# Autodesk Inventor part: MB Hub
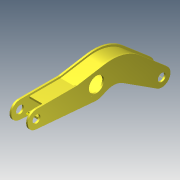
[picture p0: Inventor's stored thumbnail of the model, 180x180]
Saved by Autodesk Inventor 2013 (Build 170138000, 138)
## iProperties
Created: 2012-03
Part Number: MB Hub
Material: Steel, Mild
Document SubType Name: Modeling
Designer: DTS
Density: 7.86 g/cm^3
Mass: 191617 g
Surface Area: 27575.3 cm^2
Volume: 24378.7 cm^3
Author: DTS
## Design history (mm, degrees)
node "Blocks"
  sketch "Weldment"
    geometry: L1 (-698.696, -99.621)-(-13.913, -159.394); L2 (303.472, -136.555)-(697.708, -389.848); L3 (816.698, -229.669)-(500.453, 40.369); L4 (93.224, 153.268)-(-225, 100); L5 (-225, 100)-(-690, 100); L6 (71.528, -143.121)-(105.954, -125.916); L7 (-57.997, -88.254)-(-54.949, -85.206); L8 (-57.997, -85.206)-(-54.949, -88.254); L9 (0, 0)-(-690, 0); L10 (0, 0)-(751.762, -305.717); L11 (0, 0)-(-1018.111, 0); C1 r 75 at (0, 0); C2 r 87 at (0, 0); C3 r 45 at (-690, 0); C4 r 45 at (751.762, -305.717); C5 r 1.524 at (-56.473, -86.73); A1 r 100 centre (-690, 0) between (-690, 100) and (-698.696, -99.621); A2 r 100 centre (751.762, -305.717) between (697.708, -389.848) and (816.698, -229.669); A3 r 500 centre (175.772, -339.871) between (500.453, 40.369) and (93.224, 153.268); A4 r 160 centre (0, 0) between (-13.913, -159.394) and (71.528, -143.121); A5 r 200 centre (195.364, -304.818) between (303.472, -136.555) and (105.954, -125.916); 1 further point
    constraints: 23 end point, 10 centre point, 10 point on circle, 10 tangent, 4 concentric, 1 collinear, 1 horizontal, 1 parallel, 1 perpendicular, 1 other
    dimensions: "d0" = 100 radius of A1; "d2" = 90 diameter of C3; "d3" = 100 radius of A2; "d4" = 90 diameter of C4; "d5" = 690 distance of A1.centre C1.centre; "d6" = 200 radius of A5; "d9" = 160 radius of A4; "d10" = 500 radius of A3; "d11" = 174 diameter of C2; "d12" = 12 radial gap between concentric circles of C1 C2; "d13" = 4.98854 deg angle of L1 L9 (derived); "d14" = 9.50272 deg angle of L4 L9; "d15" = 157.87 deg angle of L10 L9; "d16" = 18.3636 deg angle of L3 L10; "d17" = 10.5905 deg angle of L2 L10; "d18" = 26.5546 deg angle of L6 L9; "d19" = 465 distance of L4.end L5.end; "d40" = 811.54715 distance of L9.start L10.end
  sketch "Connector"
    geometry: L1 (157.164, 27.531)-(232.989, 74.957); L2 (483.604, 231.708)-(512.662, 249.882); L3 (76.449, -64.463)-(145.454, 17.372); L4 (449.028, 351.621)-(398.755, 320.177); L5 (509.104, 419.139)-(460.738, 361.78); L6 (526.921, 255.966)-(571.21, 267.162); L7 (232.989, 74.957)-(483.604, 231.708); L8 (398.755, 320.177)-(93.53, 129.27); L9 (529.743, 443.615)-(509.104, 419.139); L10 (79.271, 123.186)-(-24.509, 96.95); L11 (571.21, 267.162)-(630.701, 282.202); L12 (302.321, 205.82)-(305.369, 208.868); L13 (302.321, 208.868)-(305.369, 205.82); C1 r 45 at (0, 0); C2 r 45 at (606.192, 379.152); C3 r 1.524 at (303.845, 207.344); A1 r 50 centre (539.176, 207.491) between (526.921, 255.966) and (512.662, 249.882); A2 r 50 centre (183.678, -14.86) between (157.164, 27.531) and (145.454, 17.372); A3 r 50 centre (422.514, 394.012) between (449.028, 351.621) and (460.738, 361.78); A4 r 50 centre (67.016, 171.661) between (79.271, 123.186) and (93.53, 129.27); A5 r 100 centre (606.192, 379.152) between (630.701, 282.202) and (529.743, 443.615); A6 r 100 centre (0, 0) between (-24.509, 96.95) and (76.449, -64.463); 1 further point
    constraints: 26 end point, 12 point on circle, 9 centre point
  sketch "Base"
    geometry: L1 (278.529, -481.687)-(299.453, -447.453); L2 (295.917, -416.857)-(172.052, -291.319); L3 (95.022, -681.286)-(272.857, -489.184); L4 (108.329, 19.101)-(158.403, -264.884); L5 (-249.445, -802.646)-(-108.413, 18.617); L6 (3.19, -856.093)-(33.762, -830.109); L7 (48.097, -808.832)-(84.242, -699.551); L8 (-13, -862.043)-(-199.378, -862.043); L9 (37.419, -377.546)-(40.467, -374.498); L10 (37.419, -374.498)-(40.467, -377.546); C1 r 40 at (0, -600); C2 r 40 at (0, 0); C3 r 1.524 at (38.943, -376.022); A1 r 47.5 centre (238, -456.916) between (272.857, -489.184) and (278.529, -481.687); A2 r 25 centre (278.122, -434.416) between (299.453, -447.453) and (295.917, -416.857); A3 r 50 centre (207.644, -256.202) between (158.403, -264.884) and (172.052, -291.319); A4 r 50 centre (131.713, -715.252) between (95.022, -681.286) and (84.242, -699.551); A5 r 110 centre (0, 0) between (108.329, 19.101) and (-108.413, 18.617); A6 r 25 centre (-13, -837.043) between (-15.705, -861.897) and (3.19, -856.093); A7 r 47.5 centre (3, -793.916) between (33.762, -830.109) and (48.097, -808.832); A8 r 50.8 centre (-199.378, -811.243) between (-249.445, -802.646) and (-199.378, -862.043); 1 further point
    constraints: 20 end point, 16 point on circle, 11 centre point
  sketch "CenterSpan"
    geometry: L1 (273.969, -185.044)-(234.974, -284.945); L2 (36.362, 93.155)-(259.933, 5.887); L3 (12.317, -103.463)-(-16.542, -98.622); L4 (180.828, -183.299)-(-38.18, -97.813); L5 (437.598, -26.221)-(296.603, -162.71); L6 (-23.266, 102.39)-(214.339, 156.38); L7 (495.815, 30.136)-(437.598, -26.221); L8 (214.339, 156.38)-(404.104, 199.5); L9 (110.262, -93.996)-(113.31, -90.948); L10 (110.262, -90.948)-(113.31, -93.996); C1 r 82 at (0, 0); C2 r 82 at (223.572, -87.268); C3 r 50 at (426.262, 101.986); C4 r 58.472 at (158.121, -254.947); C5 r 1.524 at (111.786, -92.472); A1 r 90 centre (-2.571, -192.223) between (81.268, -224.948) and (12.317, -103.463); A2 r 60 centre (329.861, -206.861) between (290.003, -162.013) and (273.969, -185.044); A3 r 100 centre (223.572, -87.268) between (290.003, -162.013) and (259.933, 5.887); A4 r 100 centre (0, 0) between (36.362, 93.155) and (-16.542, -98.622); A5 r 105 centre (223.572, -87.268) between (189.942, -186.736) and (296.603, -162.71); A6 r 105 centre (0, 0) between (-23.266, 102.39) and (-38.18, -97.813); A7 r 100 centre (426.262, 101.986) between (495.815, 30.136) and (404.104, 199.5); A8 r 82.5 centre (158.121, -254.947) between (81.268, -224.948) and (234.974, -284.944); 1 further point
    constraints: 20 end point, 16 point on circle, 13 centre point
  sketch "Arm"
    geometry: L1 (-25.496, -107.005)-(137.409, -145.82); L2 (2597.068, -901.099)-(2521.421, -896.025); L3 (2257.231, -771.408)-(2076.35, -579.673); L4 (2076.35, -579.673)-(2063.205, -583.463); L5 (2043.846, -578.704)-(1704.981, -254.849); L6 (1379.251, -95.221)-(16.283, 108.788); L7 (137.409, -145.82)-(1374.243, -440.518); L8 (1601.431, -691.827)-(2199.578, -1052.198); L9 (2469.644, -1123.775)-(2592.355, -1120.82); L10 (1293.329, -509.09)-(1296.377, -506.042); L11 (1293.329, -506.042)-(1296.377, -509.09); C1 r 40.528 at (0, 0); C2 r 40.528 at (2589.706, -1010.852); C3 r 1.524 at (1294.853, -507.566); A1 r 400 centre (2548.19, -496.921) between (2482.623, -891.511) and (2521.421, -896.025); A2 r 110 centre (2589.706, -1010.852) between (2597.994, -1120.539) and (2597.068, -901.099); A3 r 400 centre (2548.19, -496.921) between (2257.231, -771.408) and (2482.623, -891.511); A4 r 20 centre (2057.664, -564.246) between (2043.846, -578.704) and (2063.205, -583.463); A5 r 600 centre (1290.432, -688.61) between (1704.981, -254.849) and (1379.251, -95.221); A6 r 70 centre (1358.018, -508.612) between (1423.227, -534.065) and (1374.243, -440.518); A7 r 100 centre (1516.382, -570.427) between (1423.227, -534.065) and (1519.438, -670.38); A8 r 150 centre (1524.023, -820.31) between (1601.431, -691.827) and (1519.438, -670.38); A9 r 500 centre (2457.606, -623.92) between (2199.578, -1052.198) and (2469.644, -1123.775); A10 r 110 centre (0, 0) between (16.283, 108.788) and (-25.496, -107.005); 1 further point
    constraints: 22 end point, 20 point on circle, 13 centre point
  sketch "Bucket"
    geometry: L1 (0, -20)-(-640.824, -20); L2 (99.176, 0)-(99.176, 10); L3 (-180.824, 0)-(-180.824, 25); L4 (0, 0)-(-180.824, 0); L5 (-180.824, 25)-(69.176, 25); L6 (99.176, 10)-(69.176, 25); L7 (-356.679, 581.068)-(-15.346, 25); L8 (-860.363, 891.232)-(-851.481, 826.214); L9 (-515.824, 1128)-(-836.02, 941.187); L10 (-1280.042, 545.155)-(-976.734, 19.869); L11 (-630.824, -10)-(0, -10); L12 (-630.824, 0)-(0, 0); L13 (-613.369, 1053.537)-(-943.37, 660.257); L14 (-606.842, 1045.759)-(-935.709, 653.829); L15 (0, -20)-(0, -10); L16 (0, -10)-(0, 0); L17 (-356.679, 581.068)-(-508.427, 1102.579); L18 (-511.303, 1112.465)-(-515.824, 1128); L19 (-419.219, 1199.918)-(-425.141, 1166.336); L20 (-409.371, 1198.182)-(-415.292, 1164.599); L21 (-429.989, 1159.412)-(-613.369, 1053.537); L22 (-419.219, 1199.918)-(-409.371, 1198.182); L23 (0, 0)-(99.176, 0); L24 (-606.842, 1045.759)-(-424.989, 1150.752); L25 (-691.058, -5.529)-(-949.951, -5.529); L26 (-1223.594, 696.836)-(-784.605, 849.466); L27 (-1185.527, 84.913)-(-968.841, -1.886); L28 (-1246.2, 229.24)-(-1184.02, 378.858); L29 (-1183.986, 378.801)-(-1121.865, 527.323); L30 (-784.605, 849.466)-(-1109.735, 544.789); C1 r 25 at (-810.824, 898); C2 r 45 at (-1189.112, 597.66); C3 r 40 at (-1144.623, 187.025); A1 r 50 centre (-810.824, 898) between (-836.02, 941.187) and (-860.363, 891.232); A2 r 110 centre (-1144.623, 187.025) between (-1246.2, 229.24) and (-1176.471, 81.737); A3 r 105 centre (-1189.112, 597.66) between (-1223.594, 696.836) and (-1280.042, 545.155); A4 r 408 centre (-630.824, 398) between (-943.37, 660.257) and (-630.824, -10); A5 r 418 centre (-630.824, 398) between (-739.856, -5.529) and (-630.824, -20); A6 r 398 centre (-630.824, 398) between (-935.709, 653.829) and (-630.824, 0); A7 r 10 centre (-434.989, 1168.072) between (-429.989, 1159.412) and (-425.141, 1166.336); A8 r 20 centre (-434.989, 1168.072) between (-424.989, 1150.752) and (-415.292, 1164.599); A9 r 50.8 centre (-949.951, 45.271) between (-968.841, -1.886) and (-949.951, -5.529); A10 r 50.8 centre (-1074.999, 507.721) between (-1109.735, 544.789) and (-1121.865, 527.323); A11 r 50.8 centre (-932.741, 45.271) between (-976.734, 19.869) and (-932.741, -5.529); 1 further point
    constraints: 60 end point, 22 point on circle, 14 centre point
  sketch "FrontBucket"
    geometry: L1 (36.508, 713.207)-(-16.797, 670.2); L2 (-16.797, 670.2)-(-101.739, 335.484); L3 (-101.739, 335.484)-(-109.966, 2.719); L4 (8.288, -109.687)-(308.835, -86.978); L5 (308.835, -86.978)-(319.542, -83.051); L6 (19.324, 520.756)-(99.155, 741.781); L7 (99.155, 741.781)-(80.344, 748.575); L8 (80.344, 748.575)-(36.508, 713.207); L9 (1233.625, 258.517)-(1200.234, 261.682); L10 (1200.234, 261.682)-(1143.868, 239.874); L11 (1143.868, 239.874)-(1177.667, 236.867); L12 (1177.667, 236.867)-(1233.625, 258.517); L13 (967.076, 171.475)-(1143.868, 239.874); L14 (1181.276, 227.541)-(976.097, 148.159); L15 (976.097, 148.159)-(967.076, 171.475); L16 (1237.234, 249.191)-(1233.625, 258.517); L17 (1177.667, 236.867)-(1181.276, 227.541); L18 (1181.276, 227.541)-(1237.234, 249.191); L19 (332.219, -99.88)-(327.869, -88.635); L20 (332.219, -99.88)-(340.093, -96.834); L21 (327.869, -88.635)-(326.446, -84.958); L22 (630.662, 15.585)-(695.946, 40.843); L23 (340.093, -96.834)-(630.662, 15.585); L24 (971.406, 160.283)-(964.544, 144.762); L25 (971.406, 160.283)-(969.963, 164.014); L26 (695.946, 40.843)-(690.173, 55.765); L27 (969.963, 164.014)-(690.173, 55.765); L28 (695.946, 40.843)-(964.544, 144.762); L29 (271.723, 1081.905)-(246.908, 1104.472); L30 (246.908, 1104.472)-(15.69, 814.708); L31 (11.012, 759.335)-(43.462, 700.624); L32 (47.21, 660.849)-(-0.759, 514.651); L33 (556.412, -14.214)-(696.307, 39.911); L34 (696.307, 39.911)-(695.946, 40.843); L35 (594.585, 649.257)-(271.723, 1081.905); L36 (459.694, 596.673)-(459.353, 596.937); L37 (459.353, 596.937)-(498.23, 611.978); L38 (1112.062, 227.901)-(576.694, 642.28); L39 (995.062, 182.294)-(998.041, 183.455); L40 (499.228, 612.083)-(459.694, 596.673); L41 (459.694, 596.673)-(526.939, 544.624); L42 (606.946, 482.699)-(686.952, 420.773); L43 (766.958, 358.848)-(846.965, 296.922); L44 (926.971, 234.997)-(985.819, 189.448); L45 (995.055, 182.3)-(995.062, 182.294); L46 (998.041, 183.455)-(1130.882, 235.237); L47 (985.819, 189.448)-(995.055, 182.3); L48 (1130.882, 235.237)-(595.514, 649.616); C1 r 60 at (0, 0); C2 r 85 at (-189.66, 366.918); C3 r 25 at (54.772, 783.522); C4 r 62.5 at (-189.66, 366.918); A1 r 110 centre (0, 0) between (-109.966, 2.719) and (8.288, -109.687); A2 r 408 centre (403.06, 382.155) between (19.324, 520.756) and (16.94, 513.969); A3 r 50 centre (54.772, 783.522) between (15.69, 814.708) and (11.012, 759.335); A4 r 50 centre (-0.298, 676.437) between (47.21, 660.849) and (43.462, 700.624); A5 r 425 centre (403.06, 382.155) between (-0.759, 514.651) and (556.412, -14.214); 1 further point
    constraints: 96 end point, 10 point on circle, 9 centre point
  sketch "A$C70327705"
    geometry: L1 (1293.342, 14.877)-(652.519, 14.877); L2 (1112.519, 47.877)-(1112.519, 51.877); L3 (652.519, 25)-(652.519, 14.997); L4 (652.519, 0)-(437.177, 0); L5 (437.177, 0)-(416.627, 29.348); L6 (662.519, 24.877)-(652.519, 24.877); L7 (1392.519, 34.877)-(1392.519, 44.877); L8 (1112.519, 34.877)-(1112.519, 59.877); L9 (1293.342, 34.877)-(1112.519, 34.877); L10 (1112.519, 59.877)-(1362.519, 59.877); L11 (1392.519, 44.877)-(1362.519, 59.877); L12 (936.663, 615.946)-(1277.997, 59.877); L13 (432.979, 926.11)-(441.861, 861.091); L14 (777.519, 1162.877)-(457.322, 976.064); L15 (116.871, 116.614)-(247.396, 77.132); L16 (100.413, 392.297)-(47.142, 264.117); L17 (374.881, 853.013)-(360.531, 832.814); L18 (440.113, 873.889)-(374.881, 853.013); L19 (9.07, 588.157)-(247.396, 77.132); L20 (662.519, 24.877)-(1293.342, 24.877); L21 (662.519, 34.877)-(1293.342, 34.877); L22 (679.974, 1088.415)-(349.973, 695.135); L23 (686.501, 1080.636)-(357.633, 688.707); L24 (1293.342, 14.877)-(1293.342, 24.877); L25 (1293.342, 24.877)-(1293.342, 34.877); L26 (936.663, 615.946)-(784.916, 1137.456); L27 (782.039, 1147.342)-(777.519, 1162.877); L28 (874.123, 1234.796)-(868.202, 1201.213); L29 (883.971, 1233.059)-(878.05, 1199.476); L30 (863.354, 1194.289)-(679.974, 1088.415); L31 (874.123, 1234.796)-(883.971, 1233.059); L32 (1293.342, 34.877)-(1392.519, 34.877); L33 (686.501, 1080.636)-(868.354, 1185.629); L34 (652.519, 0)-(652.519, 14.997); L35 (602.285, 29.348)-(293.569, 29.348); L36 (259.584, 50.998)-(247.396, 77.132); L37 (69.748, 731.714)-(508.737, 884.343); C1 r 25 at (482.519, 932.877); C2 r 45 at (104.231, 632.537); A1 r 50 centre (482.519, 932.877) between (457.322, 976.064) and (432.979, 926.11); A2 r 40 centre (148.72, 221.902) between (162.34, 259.512) and (186.286, 208.165); A3 r 110 centre (148.72, 221.902) between (47.142, 264.117) and (116.871, 116.614); A4 r 105 centre (104.231, 632.537) between (69.748, 731.714) and (9.07, 588.157); A5 r 408 centre (662.519, 432.877) between (349.973, 695.135) and (662.519, 24.877); A6 r 398 centre (662.519, 432.877) between (357.633, 688.707) and (662.519, 34.877); A7 r 37.5 centre (293.569, 66.848) between (259.584, 50.998) and (293.569, 29.348); A8 r 10 centre (858.354, 1202.949) between (863.354, 1194.289) and (868.202, 1201.213); A9 r 20 centre (858.354, 1202.949) between (868.354, 1185.629) and (878.05, 1199.476); 1 further point
    constraints: 74 end point, 18 point on circle, 11 centre point
  sketch "A$C60B60B97"
    geometry: 1 further point
sketch "Sketch1"
  geometry: 1 further point
  constraints: 1 other
  node "Weldment:1"
workplane "Work Plane2"
  workplane "Work Plane1"
extrude "Extrusion1" new body sketch "Sketch1" stored distance "d43" = 10; taper "d44" = 0 deg
workplane "Work Plane4"
  workplane "Work Plane3"
extrude "Extrusion2" new body sketch "Sketch1" stored distance "d47" = 10; taper "d48" = 0 deg
sketch "Sketch2"
  geometry: L1 (0, 465)-(0, 0) reference; L2 (53.268, 783.224)-(0, 465) reference; L3 (-329.669, 1506.698)-(-59.631, 1190.453) reference; L4 (-236.555, 993.472)-(-489.848, 1387.708) reference; L5 (-243.121, 761.528)-(-225.916, 795.954) reference; L6 (-199.621, -8.696)-(-259.394, 676.087) reference; L7 (-209.871, 1335.602)-(-74.841, 1177.465); L8 (33.542, 786.526)-(-20, 466.662); L9 (-20, 466.662)-(-20, 107.363); L10 (-429.779, 1331.213)-(-219.728, 1004.283); L11 (-208.026, 787.013)-(-225.231, 752.587); L12 (-239.47, 677.826)-(-188.393, 92.665); L13 (-100, 0)-(-199.621, -8.696); L14 (-188.393, 92.665)-(-20, 107.363); L15 (-243.967, 1352.979)-(-379.3, 1363.646); L16 (-429.779, 1331.213)-(-379.3, 1363.646); C1 r 45 at (-100, 0) reference; C2 r 45 at (-405.717, 1441.762) reference; A1 r 500 centre (-439.871, 865.772) between (53.268, 783.224) and (-59.631, 1190.453) reference; A2 r 200 centre (-404.818, 885.364) between (-225.916, 795.954) and (-236.555, 993.472) reference; A3 r 160 centre (-100, 690) between (-243.121, 761.528) and (-259.394, 676.087) reference; A4 r 480 centre (-439.871, 865.772) between (33.542, 786.526) and (-74.841, 1177.465); A5 r 220 centre (-404.818, 885.364) between (-208.026, 787.013) and (-219.728, 1004.283); A6 r 140 centre (-100, 690) between (-225.231, 752.587) and (-239.47, 677.826); A7 r 50 centre (-247.895, 1303.134) between (-209.871, 1335.602) and (-243.967, 1352.979)
  constraints: 20 end point, 8 point on circle, 4 centre point, 2 perpendicular, 2 tangent, 1 parallel, 7 other
  dimensions: "d49" = 20 distance between parallel lines of L3 L7; "d50" = 20 distance between parallel lines of L4 L10 (= d49); "d55" = 100 distance from line of L13 L12.end; "d63" = 50 radius of A7; "d64" = 45 deg angle of L15 L7; "d65" = 60 distance of L10.start L15.end (= 3 x Platethickness); "d66" = 80 distance from line of C2.centre L16
extrude_surface "ExtrusionSrf1" dims "d57" = 10, "d58" = 0
extrude_surface "ExtrusionSrf2" dims "d59" = 10, "d60" = 0
thicken "Thicken1" dims "d61" = 20 (= Platethickness)
thicken "Thicken2" dims "d62" = 20 (= Platethickness)
workpoint "Work Point1"
  workaxis "Work Axis1"
workaxis "Work Axis2"
body "Solid1"
body "Solid2"
body "Srf1"
body "Srf2"
body "Solid3"
body "Solid4"
node "Bucket:1"
other parameters: "d41" = 105 (= 0.5 x Width), "Platethickness" = 20, "d45" = -105 (= -0.5 x Width)
